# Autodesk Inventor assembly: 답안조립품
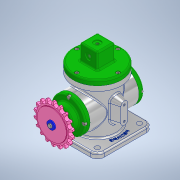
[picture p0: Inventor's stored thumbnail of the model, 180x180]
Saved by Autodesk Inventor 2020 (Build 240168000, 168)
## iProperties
Created: 2021-03
Part Number: 답안조립품
Document SubType Name: Assembly
Designer: USER
Author: USER
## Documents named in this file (19)
- C:\Users\USER\Desktop\710306V1009\답안조립품.iam
- C:\Users\USER\Desktop\710306V1009\본체.ipt
- C:\Users\USER\Desktop\710306V1009\E-링.ipt
- C:\Users\USER\Desktop\710306V1009\덮개.ipt
- C:\Users\USER\Desktop\710306V1009\뒤커버.ipt
- C:\Users\USER\Desktop\710306V1009\링크.ipt
- C:\Users\USER\Desktop\710306V1009\멈춤나사 M3.ipt
- C:\Users\USER\Desktop\710306V1009\베어링 17 x 40 x 12.ipt
- C:\Users\USER\Desktop\710306V1009\볼트 M4 x 8.ipt
- C:\Users\USER\Desktop\710306V1009\볼트 M4 x 10.ipt
- C:\Users\USER\Desktop\710306V1009\스프로킷.ipt
- C:\Users\USER\Desktop\710306V1009\슬라이더.ipt
- C:\Users\USER\Desktop\710306V1009\앞커버.ipt
- C:\Users\USER\Desktop\710306V1009\오일 실 17 30 8.ipt
- C:\Users\USER\Desktop\710306V1009\와셔 4x16.ipt
- C:\Users\USER\Desktop\710306V1009\클레비스 핀 6 x 22.ipt
- 클레비스 핀 6 x 22.ipt
- C:\Users\USER\Desktop\710306V1009\키 4 x 4 x 12.ipt
- C:\Users\USER\Desktop\710306V1009\편심축.ipt
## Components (1 placed, 1 different names)
1. E-링:1
